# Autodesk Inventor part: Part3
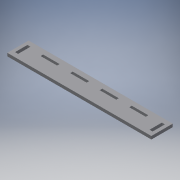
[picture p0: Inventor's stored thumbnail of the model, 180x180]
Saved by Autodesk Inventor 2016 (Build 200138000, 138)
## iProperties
Created: 2017-06
Part Number: Part3
Material: Generic
Document SubType Name: Modeling
Designer: laboratorioesan
Density: 1 g/cm^3
Appearance: Default
Author: laboratorioesan
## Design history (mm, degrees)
sketch "Sketch1"
  geometry: L1 (0, -27.5)-(0, -102.5) reference; L2 (0, -102.5)-(18.5, -102.5) reference; L3 (18.5, -27.5)-(18.5, -102.5) reference; L4 (0, -27.5)-(18.5, -27.5) reference; L5 (0, 0)-(18.5, 0) reference; L6 (0, -130)-(18.5, -130) reference; L7 (-20, 0)-(857, 0); L8 (857, 0)-(857, -130); L9 (857, -130)-(-20, -130); L10 (-20, -130)-(-20, 0); L11 (0, -27.5)-(18.5, -27.5); L12 (18.5, -27.5)-(18.5, -102.5); L13 (18.5, -102.5)-(0, -102.5); L14 (0, -102.5)-(0, -27.5); L15 (818.5, -27.5)-(837, -27.5); L16 (837, -27.5)-(837, -102.5); L17 (837, -102.5)-(818.5, -102.5); L18 (818.5, -102.5)-(818.5, -27.5)
  constraints: 24 end point, 6 parallel, 3 horizontal, 3 perpendicular, 2 collinear, 2 horizontal alignment, 2 point on line
  dimensions: "d0" = 20 horizontal distance of L7.start L1.start; "d1" = 20 horizontal distance of L8.end L16.end; "d2" = 800 distance of L17.end L2.end
extrude "Extrusion1" new body sketch "Sketch1" distance "d3" = 18.5; taper "d4" = 0 deg
sketch "Sketch2"
  geometry: L1 (837, -102.5)-(837, -27.5) reference; L2 (837, -27.5)-(818.5, -27.5) reference; L3 (818.5, -27.5)-(818.5, -102.5) reference; L4 (818.5, -102.5)-(837, -102.5) reference; L5 (18.5, -27.5)-(0, -27.5) reference; L6 (0, -27.5)-(0, -102.5) reference; L7 (0, -102.5)-(18.5, -102.5) reference; L8 (18.5, -102.5)-(18.5, -27.5) reference; L9 (-20, 0)-(857, 0) reference; L10 (857, 0)-(857, -130) reference; L11 (857, -130)-(-20, -130) reference; L12 (-20, -130)-(-20, 0) reference; L13 (738.5, -45.5)-(638.5, -45.5); L14 (638.5, -45.5)-(638.5, -30); L15 (638.5, -30)-(738.5, -30); L16 (738.5, -30)-(738.5, -45.5); L17 (558.5, -45.5)-(458.5, -45.5); L18 (458.5, -45.5)-(458.5, -30); L19 (458.5, -30)-(558.5, -30); L20 (558.5, -30)-(558.5, -45.5); L21 (378.5, -45.5)-(278.5, -45.5); L22 (278.5, -45.5)-(278.5, -30); L23 (278.5, -30)-(378.5, -30); L24 (378.5, -30)-(378.5, -45.5); L25 (198.5, -45.5)-(98.5, -45.5); L26 (98.5, -45.5)-(98.5, -30); L27 (98.5, -30)-(198.5, -30); L28 (198.5, -30)-(198.5, -45.5); 1 further point
  constraints: 32 end point, 8 parallel, 6 point on line, 4 horizontal, 4 perpendicular, 3 collinear
  dimensions: "d5" = 15.5 distance of L25.end L26.end; "d6" = 100 distance of L25.start L25.end; "d7" = 80 distance of L21.end L25.start; "d8" = 80 distance of L17.end L21.start; "d9" = 80 distance of L13.end L17.start; "d10" = 30 vertical distance of L9.end L15.end; "d11" = 80 horizontal distance of L2.end L13.start
extrude "Extrusion2" cut sketch "Sketch2" distance "d12" = 18.5; taper "d13" = 0 deg
body "Solid1"
node "Reference1"
node "Reference2"
node "Reference3"
node "Projected Loop1"
